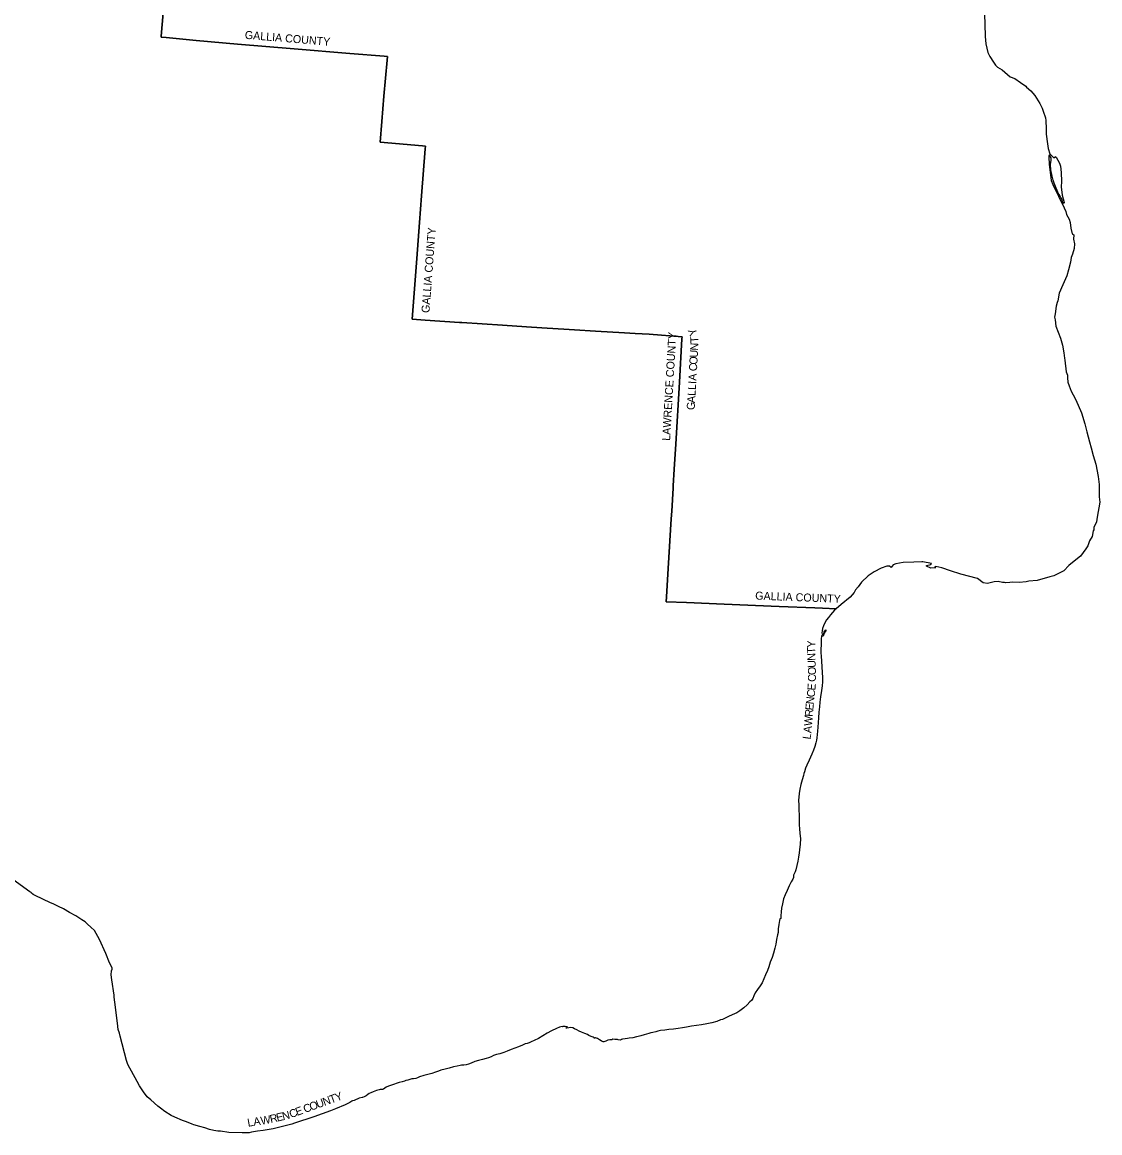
# Model space of a CAD drawing. Extents: x 1715311 to 2083412, y 146837 to 553079.
# Drawn here: x 1927546 to 2062189, y 146837 to 285591 of the extents above; entities that cross this region are included whole.
import ezdxf

# ---------------------------------------------------------------- set-up
doc = ezdxf.new("R2010")
doc.units = 0
doc.layers.add('GM_X_Adjacent_County', color=7, linetype='Continuous')
doc.layers.add('GM_X_Adjacent_County_Text', color=7, linetype='Continuous')

msp = doc.modelspace()

# ---------------------------------------------------------------- linework, layer by layer
at = {"layer": 'GM_X_Adjacent_County'}
for points in [[(1946067, 297426), (1944907, 283849), (1944903, 283729), (1945544, 283670), (1949278, 283311), (1954438, 282859), (1961539, 282259), (1968499, 281682), (1972774, 281329), (1973182, 281296), (1973148, 280848), (1972730, 276350), (1972469, 273167), (1972286, 270595), (1977551, 270131), (1977918, 270099), (1977893, 269769), (1977440, 263895), (1977181, 260548), (1976836, 256069), (1976252, 248479), (1977883, 248369), (1982174, 248080), (1982477, 248059), (1987557, 247725), (1990569, 247526), (1992472, 247400), (1995909, 247190), (1996544, 247151), (1999180, 246990), (2002818, 246768), (2004152, 246687), (2005876, 246607), (2010027, 246281), (2009980, 246018), (2009662, 240602), (2009205, 232852), (2009016, 229762), (2008888, 227673), (2008870, 227386), (2008698, 224504), (2008642, 223563), (2008270, 217353), (2008056, 213785), (2008020, 213174), (2010538, 213073), (2015261, 212882), (2022114, 212606), (2026592, 212426), (2027533, 212388), (2029251, 212319), (2029041, 212132), (2028799, 211843), (2028534, 211550), (2028291, 211237), (2028032, 210913), (2027886, 210615), (2027680, 210195), (2027544, 209857), (2027488, 209562), (2027473, 209313), (2027499, 209144), (2027553, 209089), (2027605, 209127), (2027692, 209235), (2027731, 209351), (2027756, 209470), (2027805, 209563), (2027880, 209644), (2027946, 209660), (2027979, 209621), (2027959, 209530), (2027831, 209372), (2027756, 209245), (2027729, 209125), (2027672, 208986), (2027593, 208878), (2027533, 208902), (2027475, 208952), (2027433, 208919), (2027367, 208521), (2027358, 208178), (2027385, 207733), (2027351, 207343), (2027348, 206791), (2027380, 206390), (2027423, 205769), (2027456, 205063), (2027489, 204343), (2027534, 203703), (2027539, 203175), (2027494, 202681), (2027406, 202095), (2027308, 201299), (2027210, 200626), (2027170, 200036), (2027099, 199378), (2027043, 198699), (2026992, 198079), (2026947, 197521), (2026910, 196997), (2026876, 196596), (2026842, 196163), (2026775, 195907), (2026728, 195544), (2026581, 195113), (2026405, 194635), (2026224, 194150), (2026039, 193763), (2025865, 193384), (2025580, 192784), (2025434, 192389), (2025306, 191933), (2025216, 191716), (2025152, 191489), (2024984, 190940), (2024829, 190369), (2024703, 189754), (2024630, 189248), (2024579, 188760), (2024540, 188397), (2024572, 187758), (2024590, 187189), (2024619, 186529), (2024644, 185780), (2024637, 185265), (2024681, 184838), (2024727, 184239), (2024782, 183586), (2024741, 182906), (2024678, 182175), (2024625, 181797), (2024554, 181282), (2024463, 180788), (2024336, 180237), (2024221, 179696), (2024117, 179440), (2023918, 179016), (2023903, 178733), (2023827, 178541), (2023618, 178179), (2023385, 177706), (2023120, 177113), (2022871, 176549), (2022688, 176054), (2022528, 175442), (2022423, 174901), (2022379, 174450), (2022356, 173926), (2022339, 173607), (2022271, 173577), (2022207, 173551), (2022152, 173379), (2022072, 172872), (2022017, 172328), (2021982, 171859), (2021899, 171549), (2021804, 171000), (2021693, 170395), (2021584, 169886), (2021425, 169276), (2021238, 168737), (2021013, 168140), (2020832, 167589), (2020655, 167123), (2020436, 166562), (2020221, 166065), (2019986, 165588), (2019737, 165180), (2019422, 164745), (2019141, 164321), (2018978, 163956), (2018820, 163613), (2018667, 163381), (2018463, 163213), (2018130, 162844), (2017727, 162462), (2017208, 162067), (2016818, 161825), (2016265, 161573), (2015790, 161363), (2015317, 161108), (2015039, 161002), (2014815, 160964), (2014322, 160746), (2013698, 160560), (2013095, 160463), (2012424, 160333), (2011804, 160241), (2011175, 160147), (2010565, 160054), (2010034, 159964), (2009488, 159870), (2008911, 159804), (2008321, 159731), (2007826, 159677), (2007314, 159605), (2006960, 159549), (2006697, 159469), (2006357, 159351), (2006113, 159307), (2005857, 159255), (2005276, 159083), (2004863, 158947), (2004497, 158879), (2004303, 158843), (2003834, 158695), (2003392, 158650), (2003181, 158602), (2002867, 158557), (2002550, 158549), (2002430, 158488), (2002284, 158424), (2002004, 158453), (2001932, 158493), (2001601, 158503), (2001355, 158539), (2001223, 158456), (2000978, 158439), (2000712, 158405), (2000460, 158284), (2000209, 158203), (2000155, 158215), (2000011, 158247), (1999907, 158309), (1999692, 158455), (1999429, 158611), (1999183, 158689), (1999069, 158625), (1999002, 158717), (1998874, 158773), (1998623, 158855), (1998363, 159007), (1998182, 159101), (1997833, 159239), (1997440, 159393), (1997156, 159547), (1996853, 159715), (1996572, 159835), (1996346, 159969), (1996113, 160001), (1995831, 159934), (1995608, 159901), (1995510, 159923), (1995532, 159965), (1995666, 160026), (1995652, 160064), (1995388, 160120), (1995153, 160133), (1995069, 160079), (1995003, 160103), (1994691, 160018), (1994286, 159879), (1993698, 159565), (1993146, 159281), (1992593, 158935), (1992043, 158605), (1991519, 158365), (1991134, 158212), (1990870, 158067), (1990640, 158010), (1990375, 157947), (1990059, 157802), (1989547, 157587), (1989094, 157395), (1988650, 157238), (1988137, 157035), (1987709, 156865), (1987208, 156710), (1986820, 156605), (1986443, 156474), (1986153, 156307), (1985827, 156192), (1985500, 156127), (1985048, 156014), (1984579, 155872), (1984115, 155725), (1983628, 155548), (1983312, 155427), (1983032, 155314), (1982735, 155281), (1982427, 155266), (1982285, 155239), (1981878, 155163), (1981431, 155060), (1980913, 154924), (1980396, 154797), (1979840, 154651), (1979573, 154542), (1979193, 154393), (1978742, 154258), (1978242, 154120), (1977747, 153995), (1977205, 153834), (1976925, 153717), (1976720, 153616), (1976420, 153595), (1976238, 153587), (1975727, 153428), (1975483, 153369), (1975311, 153295), (1975038, 153220), (1974656, 153121), (1974269, 153014), (1974043, 152915), (1973675, 152788), (1973325, 152665), (1973018, 152545), (1972852, 152424), (1972690, 152300), (1972580, 152257), (1972414, 152255), (1972264, 152249), (1972143, 152213), (1971825, 152120), (1971411, 151959), (1971100, 151816), (1970910, 151739), (1970742, 151609), (1970504, 151464), (1970262, 151331), (1970047, 151264), (1970012, 151253), (1969665, 151162), (1969469, 151098), (1969181, 150945), (1969039, 150864), (1968830, 150816), (1968726, 150786), (1968496, 150641), (1967910, 150322), (1966684, 149821), (1966053, 149601), (1964005, 148844), (1961582, 148037), (1961247, 147904), (1958890, 147346), (1957671, 147120), (1956964, 147042), (1956180, 146913), (1955920, 146851), (1955045, 146837), (1953374, 146870), (1952307, 147056), (1951987, 147024), (1951489, 147116), (1950932, 147266), (1950360, 147440), (1949736, 147640), (1949001, 147816), (1948775, 147908), (1948077, 148219), (1947594, 148393), (1946605, 148779), (1946175, 149002), (1945379, 149503), (1944836, 149925), (1944494, 150160), (1943605, 150971), (1943159, 151348), (1942697, 151943), (1942204, 152705), (1941906, 153226), (1940757, 155371), (1940569, 155855), (1939791, 158910), (1939705, 159289), (1939555, 159739), (1939473, 160554), (1939125, 163160), (1939051, 163799), (1939043, 164046), (1938753, 165965), (1938672, 166590), (1938700, 167075), (1938789, 167300), (1938785, 167426), (1938442, 168067), (1938014, 169252), (1937197, 170999), (1936567, 172109), (1936128, 172538), (1935716, 172886), (1935426, 173201), (1934981, 173429), (1934263, 173952), (1933444, 174355), (1932710, 174836), (1932062, 175128), (1931514, 175413), (1931395, 175456), (1931074, 175571), (1929165, 176487), (1928910, 176618), (1928724, 176795), (1928665, 176840), (1928500, 176957), (1926382, 178488)], [(2047804, 286627), (2047880, 283904), (2047878, 283797), (2047966, 282898), (2048191, 281819), (2048445, 281292), (2048888, 280598), (2049171, 280234), (2049415, 279995), (2049707, 279789), (2050002, 279659), (2050986, 278773), (2051562, 278571), (2052293, 278072), (2052957, 277595), (2053023, 277485), (2053572, 276998), (2054069, 276429), (2054690, 275443), (2054975, 274856), (2055129, 274477), (2055422, 273641), (2055446, 273325), (2055438, 272906), (2055474, 272672), (2055494, 272556), (2055488, 271596), (2055655, 270379), (2055755, 269822), (2055949, 269166), (2056450, 268650), (2056559, 268712), (2056623, 268818), (2056725, 268728), (2057156, 267985), (2057272, 267619), (2057375, 266825), (2057393, 265684), (2057363, 265010), (2057503, 263979), (2057748, 263068), (2057701, 262962), (2057591, 263062), (2057471, 263405), (2057096, 264067), (2057038, 264167), (2056507, 265482), (2056358, 265840), (2056254, 266370), (2056072, 267163), (2056028, 267817), (2056104, 268338), (2056102, 268656), (2055919, 268968), (2055813, 268940), (2055835, 268734), (2055857, 267863), (2056104, 265798), (2056302, 265304), (2057719, 262420), (2057960, 261934), (2058044, 261581), (2058357, 260997), (2058473, 260561), (2058567, 259854), (2058718, 259144), (2058820, 259122), (2058938, 259034), (2058906, 258471), (2059040, 257891), (2058982, 257335), (2058770, 256626), (2058627, 256182), (2058547, 255629), (2058275, 254663), (2058088, 253886), (2057555, 252790), (2057120, 251741), (2056941, 250796), (2056873, 250580), (2056759, 250108), (2056594, 249161), (2056528, 248743), (2056604, 248416), (2056689, 247636), (2057001, 246857), (2057270, 246129), (2057522, 245240), (2057689, 244292), (2057770, 243633), (2057801, 243375), (2057977, 241923), (2058136, 241486), (2058136, 241140), (2058180, 240608), (2058366, 240162), (2058603, 239489), (2058867, 239031), (2059190, 238391), (2059924, 236768), (2060306, 235412), (2060587, 234431), (2060906, 233181), (2061102, 232412), (2061359, 231454), (2061704, 230373), (2061995, 228851), (2062127, 227815), (2062097, 226779), (2062094, 226291), (2062189, 225615), (2061843, 223747), (2061773, 223187), (2061640, 222876), (2061464, 222520), (2061447, 222182), (2061367, 222065), (2061239, 221341), (2060919, 220815), (2060686, 220150), (2060447, 219794), (2059771, 218865), (2058993, 218247), (2058333, 217716), (2057716, 217027), (2057279, 216851), (2056453, 216436), (2055938, 216279), (2054378, 215839), (2053335, 215773), (2052977, 215663), (2052104, 215593), (2051301, 215619), (2050968, 215601), (2050411, 215565), (2050273, 215608), (2050044, 215579), (2049486, 215712), (2049012, 215653), (2048165, 215471), (2047631, 215555), (2046910, 216093), (2044819, 216632), (2043524, 217037), (2042449, 217438), (2041705, 217601), (2041554, 217521), (2041684, 217480), (2041666, 217412), (2041068, 217391), (2040557, 217640), (2040547, 217716), (2041076, 217853), (2041168, 217981), (2040086, 218175), (2039954, 218181), (2038960, 218124), (2037622, 218100), (2036688, 217942), (2036361, 217795), (2036102, 217475), (2035896, 217629), (2035631, 217639), (2035563, 217641), (2034879, 217399), (2033979, 216936), (2033237, 216441), (2032405, 215615), (2031983, 215029), (2031661, 214693), (2031514, 214360), (2030991, 213776), (2029856, 212824), (2029251, 212319), (2027533, 212388), (2026592, 212426), (2022114, 212606), (2015261, 212882), (2010538, 213073), (2008020, 213174), (2008056, 213785), (2008270, 217353), (2008642, 223563), (2008698, 224504), (2008870, 227386), (2008888, 227673), (2009016, 229762), (2009205, 232852), (2009662, 240602), (2009980, 246018), (2010027, 246281), (2005876, 246607), (2004152, 246687), (2002818, 246768), (1999180, 246990), (1996544, 247151), (1995909, 247190), (1992472, 247400), (1990569, 247526), (1987557, 247725), (1982477, 248059), (1982174, 248080), (1977883, 248369), (1976252, 248479), (1976836, 256069), (1977181, 260548), (1977440, 263895), (1977893, 269769), (1977918, 270099), (1977551, 270131), (1972286, 270595), (1972469, 273167), (1972730, 276350), (1973148, 280848), (1973182, 281296), (1972774, 281329), (1968499, 281682), (1961539, 282259), (1954438, 282859), (1949278, 283311), (1945544, 283670), (1944903, 283729), (1944907, 283849), (1946067, 297426)]]:
    msp.add_lwpolyline(points, dxfattribs=at)

# ---------------------------------------------------------------- texts
at = {"layer": 'GM_X_Adjacent_County_Text'}
for s, rotation, p in [('GALLIA COUNTY', 355.23005, (1955329, 283530)), ('GALLIA COUNTY', 85.60905, (1978418, 249237)), ('Y', 110.95326, (2011943, 246632)), ('LAWRENCE COUNTY', 86.64825, (2008495, 233275)), ('T', 92.59668, (2012048, 245544)), ('U', 86.65109, (2011943, 243664)), ('N', 86.55742, (2011994, 244546)), ('C', 86.67356, (2011844, 241968)), ('O', 86.66853, (2011891, 242781)), ('A', 86.67287, (2011775, 240782)), ('L', 86.67449, (2011708, 239627)), ('I', 86.67612, (2011751, 240374)), ('A', 86.67564, (2011613, 237997)), ('L', 86.67336, (2011665, 238880)), ('G', 86.67287, (2011562, 237114)), ('GALLIA COUNTY', 357.71847, (2019118, 213466)), ('Y', 89.50848, (2026623, 207453)), ('T', 90.576, (2026630, 206710)), ('N', 92.3908, (2026667, 205835)), ('U', 93.2261, (2026716, 204956)), ('C', 88.1765, (2026709, 203162)), ('O', 91.14808, (2026736, 204032)), ('E', 86.56602, (2026652, 202081)), ('N', 83.86406, (2026449, 200328)), ('C', 82.80504, (2026543, 201202)), ('E', 85.02844, (2026385, 199588)), ('W', 85.3191, (2026224, 197629)), ('R', 85.29968, (2026318, 198778)), ('A', 85.22625, (2026151, 196746)), ('L', 81.74048, (2026036, 195940)), ('N', 20.07792, (1965303, 150185)), ('T', 20.07796, (1966133, 150488)), ('Y', 20.07795, (1966836, 150745)), ('E', 20.10028, (1961889, 148937)), ('C', 20.07787, (1962877, 149298)), ('O', 20.07785, (1963641, 149578)), ('U', 20.07813, (1964472, 149881)), ('L', 10.51619, (1955775, 147578)), ('A', 7.60925, (1956497, 147712)), ('W', 10.07584, (1957420, 147837)), ('R', 12.6404, (1958603, 148048)), ('E', 13.24505, (1959409, 148229)), ('N', 13.7877, (1960147, 148403)), ('C', 20.57691, (1961129, 148652))]:
    msp.add_text(s, height=1000, rotation=rotation, dxfattribs=at).set_placement(p)

doc.saveas('drawing.dxf')
